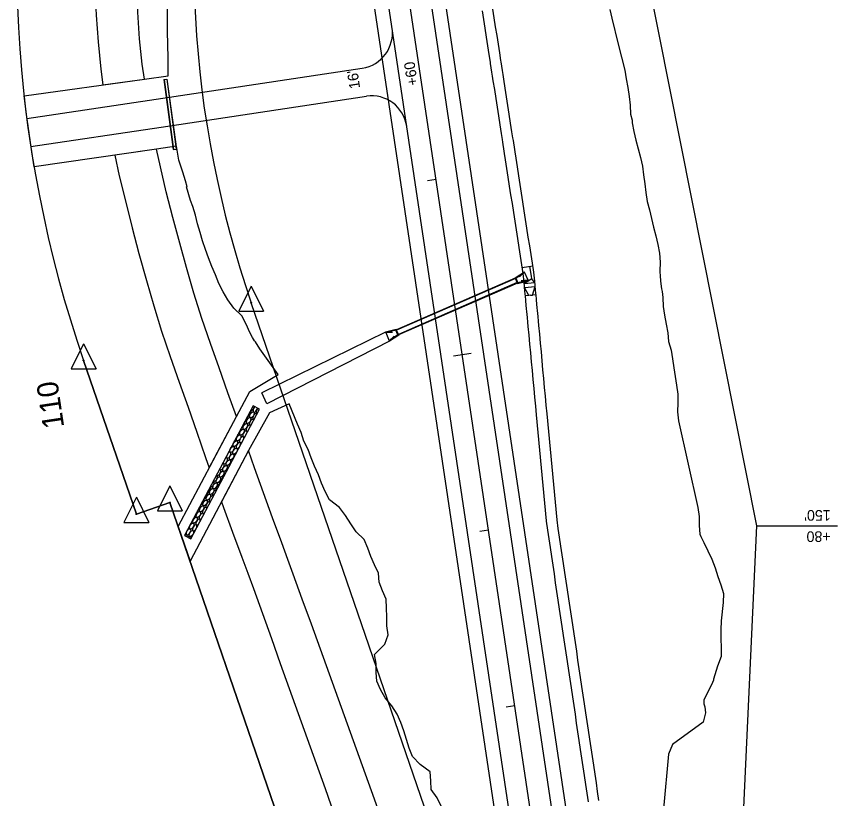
# Model space of a CAD drawing. Extents: x 609264 to 611265, y 427753 to 431566.
# Drawn here: x 610708.3 to 611171.4, y 429032.9 to 429473.9 of the extents above; entities that cross this region are included whole.
import ezdxf

# ---------------------------------------------------------------- set-up
doc = ezdxf.new("R2010")
doc.units = 0
for name, color, linetype in [('R_Drainage', 7, 'Continuous'), ('R_Drainage Stage 2', 7, 'Continuous'), ('R_Drive', 7, 'Continuous'), ('R_Drive Annot', 7, 'Continuous'), ('R_Drive Stage 2', 7, 'Continuous'), ('R_Horz Alg', 7, 'Continuous'), ('R_Horz Alg Station', 7, 'Continuous'), ('R_Horz Alg Station Annot', 7, 'Continuous'), ('R_Obliterate', 7, 'Continuous'), ('R_Proposed Const Limits', 7, 'Continuous'), ('R_Proposed Const Limits S2', 7, 'Continuous'), ('R_Proposed Road', 7, 'Continuous'), ('R_Proposed Shoulder', 7, 'Continuous'), ('R_Restraining Conditions', 7, 'Continuous'), ('R_ROW', 7, 'Continuous'), ('R_ROW Annot', 7, 'Continuous'), ('S_EXIST_ROW', 7, 'Continuous')]:
    doc.layers.add(name, color=color, linetype=linetype)

msp = doc.modelspace()

# ---------------------------------------------------------------- linework, layer by layer
at = {"layer": 'R_Drainage'}
for p, q in [((610791.37, 429438.24), (610793.18, 429438.48)), ((610791.37, 429438.24), (610796.67, 429398.8)), ((610791.53, 429438.26), (610796.84, 429398.83)), ((610793.02, 429438.46), (610798.32, 429399.03)), ((610793.18, 429438.48), (610798.49, 429399.05)), ((610796.67, 429398.8), (610798.49, 429399.05)), ((610993.59, 429332.28), (610999.53, 429333.21)), ((610989.54, 429326.52), (610994.76, 429329.97)), ((610989.93, 429326.33), (610994.88, 429329.7)), ((610994.76, 429329.97), (610992.04, 429327.02)), ((610994.88, 429329.7), (610992.04, 429327.02)), ((610994.88, 429329.7), (610994.76, 429329.97)), ((610996.87, 429325.12), (610994.88, 429329.7)), ((610989.63, 429326.3), (610922.6, 429297.15)), ((610989.72, 429326.09), (610922.7, 429296.94)), ((610990.72, 429323.8), (610923.69, 429294.64)), ((610990.81, 429323.59), (610923.79, 429294.43)), ((610989.65, 429326.25), (610989.54, 429326.52)), ((610989.92, 429326.37), (610989.65, 429326.25)), ((610989.65, 429326.25), (610990.79, 429323.65)), ((610989.92, 429326.37), (610991.05, 429323.77)), ((610991.05, 429323.77), (610990.79, 429323.65)), ((610990.79, 429323.65), (610990.9, 429323.38)), ((610990.9, 429323.38), (610996.99, 429324.85)), ((610991.04, 429323.8), (610996.87, 429325.12)), ((610996.87, 429325.12), (610992.97, 429324.87)), ((610996.99, 429324.85), (610992.97, 429324.87)), ((611000.68, 429323.62), (610994.71, 429323.06)), ((610996.87, 429325.12), (610996.99, 429324.85)), ((610994.9, 429321.06), (611000.87, 429321.62)), ((611001.31, 429316.97), (610995.33, 429316.41)), ((610916.42, 429295.89), (610846.72, 429261.7)), ((610922.51, 429297.36), (610916.42, 429295.89)), ((610916.54, 429295.62), (610916.42, 429295.89)), ((610916.42, 429295.89), (610920.44, 429295.88)), ((610922.37, 429296.95), (610916.54, 429295.62)), ((610916.54, 429295.62), (610920.44, 429295.88)), ((610916.54, 429295.62), (610918.54, 429291.05)), ((610922.36, 429296.98), (610922.63, 429297.09)), ((610923.49, 429294.38), (610922.36, 429296.98)), ((610922.63, 429297.09), (610922.51, 429297.36)), ((610923.76, 429294.49), (610922.63, 429297.09)), ((610923.49, 429294.38), (610923.76, 429294.49)), ((610923.76, 429294.49), (610923.88, 429294.23)), ((610923.48, 429294.41), (610918.54, 429291.05)), ((610918.54, 429291.05), (610921.38, 429293.72)), ((610918.54, 429291.05), (610918.65, 429290.78)), ((610923.88, 429294.23), (610918.65, 429290.78)), ((610918.65, 429290.78), (610921.38, 429293.72))]:
    msp.add_line(p, q, dxfattribs=at)
for points in [[(611007.21, 429189.51), (611001.62, 429249.25), (611001.16, 429254.24), (611000.69, 429259.23), (611000.23, 429264.21), (610999.76, 429269.2), (610999.29, 429274.18), (610998.83, 429279.17), (610998.36, 429284.16), (610997.9, 429289.14), (610997.43, 429294.13), (610996.96, 429299.11), (610996.74, 429301.49), (610996.5, 429304.1), (610996.17, 429307.6), (610996.03, 429309.09), (610995.63, 429313.38), (610995.56, 429314.07), (610995.38, 429316.07), (610995.1, 429319.06), (610994.63, 429324.03), (610994.12, 429328.91), (610993.36, 429333.78), (610992.59, 429338.72), (610991.83, 429343.66), (610991.06, 429348.6), (610990.29, 429353.54), (610989.53, 429358.48), (610988.76, 429363.43), (610987.99, 429368.37), (610987.22, 429373.31), (610986.46, 429378.25), (610985.69, 429383.19), (610984.92, 429388.13), (610984.16, 429393.07), (610983.61, 429396.62), (610983.6, 429396.63), (610983.39, 429398.01), (610982.62, 429402.95), (610982.39, 429404.45), (610982.39, 429404.46), (610981.85, 429407.89), (610981.09, 429412.83), (610980.32, 429417.77), (610979.55, 429422.72), (610978.79, 429427.66), (610978.02, 429432.6), (610977.25, 429437.54), (610976.83, 429440.22), (610976.48, 429442.48), (610975.72, 429447.42), (610975.62, 429448.06), (610974.95, 429452.36), (610974.18, 429457.3), (610973.42, 429462.24), (610972.65, 429467.18), (610971.88, 429472.12), (610971.11, 429477.07)], [(611013.18, 429190.06), (611007.6, 429249.81), (611007.13, 429254.8), (611006.67, 429259.78), (611006.2, 429264.77), (611005.73, 429269.76), (611005.27, 429274.74), (611004.8, 429279.73), (611004.34, 429284.71), (611003.87, 429289.7), (611003.4, 429294.69), (611002.94, 429299.67), (611002.72, 429302.04), (611002.47, 429304.66), (611002.14, 429308.16), (611002, 429309.64), (611001.6, 429313.94), (611001.54, 429314.63), (611001.35, 429316.62), (611001.07, 429319.62), (611000.6, 429324.62), (611000.07, 429329.69), (610999.29, 429334.7), (610998.52, 429339.64), (610997.76, 429344.58), (610996.99, 429349.52), (610996.22, 429354.46), (610995.45, 429359.4), (610994.69, 429364.35), (610993.92, 429369.29), (610993.15, 429374.23), (610992.39, 429379.17), (610991.62, 429384.11), (610990.85, 429389.05), (610990.08, 429393.99), (610989.53, 429397.54), (610989.53, 429397.55), (610989.32, 429398.93), (610988.55, 429403.87), (610988.32, 429405.37), (610988.32, 429405.38), (610987.78, 429408.81), (610987.02, 429413.75), (610986.25, 429418.7), (610985.48, 429423.64), (610984.71, 429428.58), (610983.95, 429433.52), (610983.18, 429438.46), (610982.76, 429441.14), (610982.41, 429443.4), (610981.65, 429448.34), (610981.55, 429448.98), (610980.88, 429453.28), (610980.11, 429458.22), (610979.34, 429463.16), (610978.58, 429468.1), (610977.81, 429473.05), (610977.04, 429477.99)], [(610998.94, 429326.02), (610998.79, 429327.39), (610997.93, 429332.96)], [(611000.68, 429323.62), (610998.94, 429326.02), (610998.94, 429326.02), (610994.71, 429323.06)], [(610998.32, 429316.69), (610997.32, 429316.6), (610994.9, 429321.06)], [(610998.32, 429316.69), (610999.32, 429316.78), (611000.87, 429321.62)], [(610918.65, 429290.78), (610849.48, 429255.54), (610846.72, 429261.7)], [(611030.92, 429031.02), (611030.18, 429035.97), (611029.44, 429040.91), (611028.7, 429045.86), (611027.96, 429050.8), (611027.22, 429055.75), (611026.48, 429060.69), (611025.74, 429065.64), (611025, 429070.58), (611024.26, 429075.53), (611023.52, 429080.47), (611022.78, 429085.41), (611022.04, 429090.36), (611021.3, 429095.3), (611020.56, 429100.25), (611019.82, 429105.19), (611019.08, 429110.14), (611018.34, 429115.08), (611017.6, 429120.03), (611016.86, 429124.97), (611016.12, 429129.92), (611015.38, 429134.86), (611014.64, 429139.81), (611013.9, 429144.75), (611013.16, 429149.7), (611012.42, 429154.64), (611011.68, 429159.59), (611010.94, 429164.53), (611010.2, 429169.48), (611009.46, 429174.42), (611008.72, 429179.37), (611007.98, 429184.31), (611007.23, 429189.34)], [(611036.85, 429031.91), (611036.11, 429036.85), (611035.37, 429041.8), (611034.63, 429046.74), (611033.89, 429051.69), (611033.15, 429056.63), (611032.41, 429061.58), (611031.67, 429066.52), (611030.93, 429071.47), (611030.19, 429076.41), (611029.45, 429081.36), (611028.71, 429086.3), (611027.97, 429091.25), (611027.23, 429096.19), (611026.49, 429101.14), (611025.75, 429106.08), (611025.01, 429111.03), (611024.27, 429115.97), (611023.53, 429120.92), (611022.79, 429125.86), (611022.05, 429130.81), (611021.31, 429135.75), (611020.57, 429140.7), (611019.83, 429145.64), (611019.09, 429150.59), (611018.35, 429155.53), (611017.61, 429160.48), (611016.87, 429165.42), (611016.13, 429170.37), (611015.39, 429175.31), (611014.65, 429180.26), (611013.91, 429185.2), (611013.18, 429190.06)]]:
    msp.add_lwpolyline(points, dxfattribs=at)
at = {"layer": 'R_Drainage Stage 2'}
for p, q in [((610841.76, 429254.38), (610803.09, 429181.2)), ((610845.3, 429252.51), (610841.76, 429254.38)), ((610806.62, 429179.33), (610845.3, 429252.51)), ((610803.09, 429181.2), (610806.62, 429179.33))]:
    msp.add_line(p, q, dxfattribs=at)
for centre, start_param, end_param in [((610841.31, 429253.49), 3.198655, 5.290171), ((610842.99, 429252.52), 0.98539, 5.33654), ((610844.68, 429251.55), 0.937483, 3.319225), ((610837.56, 429247), 3.490368, 6.078633), ((610839.44, 429250.24), 3.343115, 6.225887), ((610842.8, 429248.3), 6.103212, 9.748974), ((610835.68, 429243.75), 3.644118, 5.924884), ((610839.05, 429241.8), 5.787685, 10.064502), ((610840.92, 429245.05), 5.950838, 9.901349), ((610833.81, 429240.5), 3.809715, 5.759287), ((610837.17, 429238.55), 5.605187, 10.246999), ((610830.06, 429234), 4.228822, 5.34018), ((610831.93, 429237.25), 3.996754, 5.572248), ((610835.3, 429235.31), 5.383647, 10.46854), ((610828.18, 429230.75), 4.671667, 4.897335), ((610833.42, 429232.06), 5.030411, 10.821776), ((610826.11, 429223.28), 2.419988, 7.149013), ((610827.99, 429226.53), 2.184163, 7.384838), ((610831.35, 429224.59), 0.900272, 2.385544), ((610833.23, 429227.84), 1.149634, 2.136182), ((610824.24, 429220.03), 2.608579, 6.960423), ((610829.48, 429221.34), 0.706382, 2.579434), ((610822.36, 429216.78), 2.775, 6.794001), ((610825.73, 429214.84), 0.381413, 2.904403), ((610827.6, 429218.09), 0.537189, 2.748628), ((610818.61, 429210.29), 3.076707, 6.492295), ((610820.49, 429213.54), 2.929214, 6.639787), ((610823.85, 429211.59), 0.233101, 3.052716), ((610816.73, 429207.04), 3.221234, 6.347768), ((610820.1, 429205.1), 6.227043, 9.625144), ((610821.97, 429208.34), 0.088308, 3.197508), ((610812.98, 429200.54), 3.51392, 6.055081), ((610814.86, 429203.79), 3.365919, 6.203082), ((610818.22, 429201.85), 6.079825, 9.772362), ((610811.11, 429197.29), 3.669108, 5.899894), ((610816.35, 429198.6), 5.926145, 9.926042), ((610809.23, 429194.04), 3.837258, 5.731744), ((610812.6, 429192.1), 5.573864, 10.278322), ((610814.47, 429195.35), 5.760672, 10.091515), ((610805.48, 429187.55), 4.273224, 5.295777), ((610807.36, 429190.79), 4.029137, 5.539865), ((610810.72, 429188.85), 5.34235, 10.509837), ((610805.29, 429183.33), 1.850243, 7.718758), ((610808.85, 429185.6), 4.907098, 10.945089), ((610803.41, 429180.08), 5.198242, 7.342493), ((610805.09, 429179.11), 5.242117, 7.362998), ((610806.78, 429178.13), 0.867464, 1.034831), ((610808.65, 429181.38), 1.103882, 2.181934)]:
    msp.add_ellipse(centre, major_axis=(0.94, 1.62), ratio=0.517889, start_param=start_param, end_param=end_param, dxfattribs=at)
for centre in [(610841.12, 429249.27), (610837.37, 429242.77), (610839.24, 429246.02), (610835.49, 429239.53), (610831.74, 429233.03), (610833.62, 429236.28), (610829.86, 429229.78), (610831.55, 429228.81), (610829.67, 429225.56), (610825.92, 429219.06), (610827.8, 429222.31), (610824.04, 429215.81), (610820.29, 429209.32), (610822.17, 429212.56), (610818.42, 429206.07), (610816.54, 429202.82), (610812.79, 429196.32), (610814.67, 429199.57), (610810.91, 429193.07), (610807.16, 429186.57), (610809.04, 429189.82), (610806.97, 429182.35)]:
    msp.add_ellipse(centre, major_axis=(0.94, 1.62), ratio=0.517889, dxfattribs=at)
at = {"layer": 'R_Drive'}
for p, q in [((610787.05, 429427.3), (610903.29, 429444.69)), ((610789.88, 429411.54), (610905.66, 429428.87))]:
    msp.add_line(p, q, dxfattribs=at)
for centre, start, end in [((610900.34, 429464.47), 278.51, 8.51), ((610908.62, 429409.09), 8.51, 98.51)]:
    msp.add_arc(centre, 20, start, end, dxfattribs=at)
at = {"layer": 'R_Drive Stage 2'}
for p, q in [((610714.12, 429416.38), (610787.05, 429427.3)), ((610716.37, 429400.54), (610789.88, 429411.54))]:
    msp.add_line(p, q, dxfattribs=at)
msp.add_arc((611404.88, 429506.52), 696.62, 187.43434, 188.75038, dxfattribs=at)
at = {"layer": 'R_Horz Alg'}
msp.add_line((611107.78, 428294.28), (610909.26, 429621.04), dxfattribs=at)
at = {"layer": 'R_Horz Alg Station'}
for points in [[(610940.06, 429381.43), (610945.01, 429382.17)], [(610954.86, 429282.53), (610964.75, 429284.01)], [(610969.66, 429183.64), (610974.6, 429184.38)], [(610984.45, 429084.74), (610989.4, 429085.48)]]:
    msp.add_lwpolyline(points, dxfattribs=at)
at = {"layer": 'R_Obliterate'}
for p, q in [((610757.08, 429435.37), (610780.44, 429438.59)), ((610787.33, 429399.08), (610763.81, 429395.68)), ((610787.33, 429399.08), (610763.81, 429395.68)), ((610817.06, 429219.41), (610832.32, 429248.29)), ((610839.19, 429229.17), (610823.9, 429200.25))]:
    msp.add_line(p, q, dxfattribs=at)
for points in [[(610780.44, 429438.59), (610779.25, 429447.05), (610777.75, 429461.34), (610776.75, 429476.28), (610776.18, 429490.93), (610775.96, 429505.05), (610776.14, 429520.02), (610776.84, 429534.46), (610777.93, 429549.4), (610779, 429561.16)], [(610752.6, 429520.59), (610752.23, 429505.61), (610752.46, 429489.81), (610753.17, 429474.53), (610754.29, 429459.61), (610755.88, 429444.15), (610757.08, 429435.37)], [(610832.32, 429248.29), (610827.58, 429261.61), (610822.56, 429275.73), (610817.72, 429289.49), (610812.86, 429303.63), (610808.38, 429317.92), (610804.17, 429332.29), (610800.36, 429346.04), (610796.49, 429360.48), (610792.82, 429375), (610789.48, 429389.16), (610787.33, 429399.08)], [(610832.32, 429248.29), (610827.58, 429261.61), (610822.56, 429275.73), (610817.72, 429289.49), (610812.86, 429303.63), (610808.38, 429317.92), (610804.17, 429332.29), (610800.36, 429346.04), (610796.49, 429360.48), (610792.82, 429375), (610789.48, 429389.16), (610787.33, 429399.08)], [(610763.81, 429395.68), (610766.28, 429384.07), (610769.96, 429369.13), (610773.64, 429354.61), (610777.4, 429340.14), (610781.56, 429325.06), (610785.74, 429310.69), (610790.18, 429296.41), (610795.02, 429282.24), (610800.06, 429267.75), (610805.05, 429253.64), (610810.1, 429239.42), (610814.97, 429225.28), (610817.06, 429219.41)], [(610763.81, 429395.68), (610766.28, 429384.07), (610769.96, 429369.13), (610773.64, 429354.61), (610777.4, 429340.14), (610781.56, 429325.06), (610785.74, 429310.69), (610790.18, 429296.41), (610795.02, 429282.24), (610800.06, 429267.75), (610805.05, 429253.64), (610810.1, 429239.42), (610814.97, 429225.28), (610817.06, 429219.41)], [(610949.74, 428919.39), (610944.79, 428933.54), (610939.84, 428947.68), (610934.89, 428961.84), (610929.95, 428976), (610925.03, 428990.09), (610920.12, 429004.24), (610915.22, 429018.41), (610910.28, 429032.53), (610905.2, 429046.79), (610900.13, 429060.88), (610895.06, 429074.96), (610889.94, 429089.04), (610884.83, 429103.09), (610879.7, 429117.17), (610874.63, 429131.27), (610869.49, 429145.36), (610864.32, 429159.44), (610861.3, 429167.65), (610857.91, 429177.14), (610852.75, 429191.2), (610847.64, 429205.34), (610842.61, 429219.43), (610839.19, 429229.17)], [(610949.74, 428919.39), (610944.79, 428933.54), (610939.84, 428947.68), (610934.89, 428961.84), (610929.95, 428976), (610925.03, 428990.09), (610920.12, 429004.24), (610915.22, 429018.41), (610910.28, 429032.53), (610905.2, 429046.79), (610900.13, 429060.88), (610895.06, 429074.96), (610889.94, 429089.04), (610884.83, 429103.09), (610879.7, 429117.17), (610874.63, 429131.27), (610869.49, 429145.36), (610864.32, 429159.44), (610861.3, 429167.65), (610857.91, 429177.14), (610852.75, 429191.2), (610847.64, 429205.34), (610842.61, 429219.43), (610839.19, 429229.17)], [(610823.9, 429200.25), (610825.02, 429197.1), (610830.11, 429183.12), (610835.44, 429169.12), (610838.88, 429160.1), (610842.06, 429151.34), (610847.14, 429137.26), (610852.18, 429123.19), (610857.11, 429109.05), (610862.14, 429094.95), (610867.22, 429080.86), (610872.19, 429066.72), (610877.27, 429052.63), (610882.37, 429038.56), (610887.37, 429024.62)], [(610823.9, 429200.25), (610825.02, 429197.1), (610830.11, 429183.12), (610835.44, 429169.12), (610838.88, 429160.1), (610842.06, 429151.34), (610847.14, 429137.26), (610852.18, 429123.19), (610857.11, 429109.05), (610862.14, 429094.95), (610867.22, 429080.86), (610872.19, 429066.72), (610877.27, 429052.63), (610882.37, 429038.56), (610887.37, 429024.62)]]:
    msp.add_lwpolyline(points, dxfattribs=at)
at = {"layer": 'R_Proposed Const Limits'}
msp.add_line((610799.53, 429186.24), (610806.22, 429166.79), dxfattribs=at)
for points in [[(610780.44, 429438.59), (610793.86, 429440.45), (610793.8, 429445.49), (610793.84, 429450.56), (610793.46, 429465.43), (610793.45, 429465.67), (610793.43, 429470.72), (610793.61, 429485.91), (610793.78, 429490.99), (610793.9, 429501.12), (610794.52, 429506.27), (610794.82, 429511.37), (610795.03, 429516.46), (610795.33, 429521.56), (610795.79, 429526.68), (610796.02, 429531.77), (610796.36, 429536.88), (610797.31, 429542.08), (610798.22, 429552.33), (610798.86, 429557.48), (610799.3, 429562.6), (610799.71, 429567.72), (610800.73, 429572.92), (610804.25, 429598.73)], [(611042.98, 429477.72), (611044.18, 429472.85), (611047.77, 429458.22), (611051.37, 429443.59), (611052.26, 429438.67), (611053.13, 429433.74), (611053.9, 429428.8), (611054.48, 429423.83), (611054.72, 429418.81), (611055.51, 429415.42), (611055.56, 429413.88), (611056.53, 429408.97), (611057.71, 429404.09), (611059.01, 429399.23), (611060.32, 429394.37), (611061.49, 429389.49), (611062.05, 429384.52), (611062.63, 429379.55), (611063.2, 429374.58), (611063.99, 429369.64), (611065.31, 429364.79), (611066.44, 429359.9), (611067.65, 429355.02), (611068.86, 429350.15), (611070.06, 429345.27), (611070.93, 429340.35), (611071.31, 429335.35), (611071.24, 429330.28), (611071.4, 429327.27), (611071.55, 429325.27), (611071.62, 429324.58), (611072.2, 429320.31), (611072.42, 429318.84), (611072.87, 429315.36), (611073.12, 429310.34), (611073.86, 429305.4), (611074.75, 429300.47), (611075.64, 429295.55), (611076.12, 429290.57), (611077.5, 429285.72), (611078.33, 429280.79), (611079.06, 429275.84), (611079.84, 429270.9), (611080.62, 429265.96), (611081.4, 429261.02), (611081.4, 429255.97), (611081.23, 429250.89), (611081.73, 429245.91), (611092.7, 429196.99), (611093.31, 429192.03), (611093.38, 429186.98), (611093.71, 429181.97), (611094.25, 429180.76), (611095.98, 429177.26), (611098.33, 429172.55), (611100.55, 429167.83), (611102.3, 429163.04), (611103.95, 429158.23), (611105.59, 429153.42), (611107.15, 429148.6), (611106.96, 429143.51), (611105.75, 429133.22), (611105.52, 429128.13), (611105.68, 429112.99), (611103.77, 429107.65), (611101.37, 429100.21), (611101.47, 429099.77), (611100.38, 429097.03), (611097.56, 429091.55), (611096.06, 429088.49), (611096.07, 429086.27), (611096.54, 429084.73), (611097.02, 429081.36), (611095.68, 429076.1), (611078.25, 429063.38), (611075.99, 429057.99), (611073.3, 429027.25)], [(610799.53, 429186.24), (610832.32, 429248.29), (610839.91, 429262.42), (610855.94, 429272.06), (610845.62, 429286.41), (610843.06, 429290.38), (610842.58, 429291.01), (610841.38, 429292.86), (610839.98, 429295.68), (610837.84, 429300.41), (610835.37, 429305.1), (610830.95, 429309.49), (610827.48, 429314.03), (610824.94, 429318.71), (610822.42, 429323.39), (610820.57, 429328.16), (610818.48, 429332.91), (610816.69, 429337.7), (610814.89, 429342.48), (610813.3, 429347.3), (610811.85, 429352.14), (610810.44, 429356.98), (610809.19, 429361.85), (610807.71, 429366.69), (610806.51, 429370.14), (610804.2, 429377.81), (610804.49, 429377.86), (610803.54, 429381.23), (610802.14, 429386.08), (610799.85, 429392.79), (610798.64, 429400.72), (610787.33, 429399.08)], [(610947.79, 429028.69), (610945.54, 429033.41), (610942.22, 429037.97), (610941.95, 429042.99), (610941.64, 429048), (610935.93, 429052.2), (610931.71, 429056.62), (610929.88, 429061.4), (610928.31, 429066.23), (610926.75, 429071.05), (610925.17, 429075.87), (610922.93, 429080.59), (610920.03, 429085.21), (610916.22, 429089.69), (610913.62, 429094.36), (610911.56, 429099.11), (610911.12, 429104.1), (610911.17, 429109.16), (610910.28, 429114.08), (610916.11, 429120.01), (610917.96, 429125.34), (610917.19, 429130.28), (610917.13, 429135.33), (610916.99, 429140.37), (610916.79, 429145.39), (610914.71, 429150.14), (610912.96, 429154.93), (610912.58, 429159.93), (610910.32, 429164.65), (610908.08, 429169.37), (610906.55, 429174.19), (610904.35, 429178.92), (610899.86, 429183.3), (610896.91, 429187.92), (610893.89, 429192.52), (610890.56, 429197.08), (610884.93, 429201.29), (610882.39, 429205.97), (610880.41, 429210.73), (610878.62, 429215.52), (610876.47, 429220.25), (610874.51, 429225.01), (610872.8, 429229.81), (610870.46, 429234.52), (610868.94, 429239.35), (610866.85, 429244.09), (610862.02, 429255.49), (610851.09, 429250.37), (610839.19, 429229.17), (610806.22, 429166.79)]]:
    msp.add_lwpolyline(points, dxfattribs=at)
at = {"layer": 'R_Proposed Const Limits S2'}
msp.add_lwpolyline([(610787.33, 429399.08), (610718.23, 429389.1), (610714.8, 429411.32), (610712.57, 429429.21), (610780.44, 429438.59)], dxfattribs=at)
at = {"layer": 'R_Proposed Road'}
for p, q in [((611041.57, 428655.73), (610897.4, 429619.26)), ((611100.64, 428423.11), (610921.13, 429622.82))]:
    msp.add_line(p, q, dxfattribs=at)
at = {"layer": 'R_Proposed Shoulder'}
for p, q in [((611112.77, 428396.14), (610929.04, 429624)), ((611025.84, 428706.82), (610889.48, 429618.08))]:
    msp.add_line(p, q, dxfattribs=at)
at = {"layer": 'R_Restraining Conditions'}
for p, q in [((610746.15, 429279.9), (610775.93, 429193.35)), ((610794.84, 429199.86), (610963.05, 428710.9))]:
    msp.add_line(p, q, dxfattribs=at)
msp.add_lwpolyline([(610775.93, 429193.35), (610794.84, 429199.86)], dxfattribs=at)
msp.add_arc((611404.88, 429506.52), 696.62, 167.41778, 198.98444, dxfattribs=at)
at = {"layer": 'R_ROW'}
msp.add_lwpolyline([(611107.97, 428799.88), (611125.91, 429186.79), (611015.56, 429741.88)], dxfattribs=at)
at = {"layer": 'R_ROW Annot'}
msp.add_line((611125.91, 429186.79), (611171.43, 429186.79), dxfattribs=at)
at = {"layer": 'S_EXIST_ROW'}
for p, q in [((610840.74, 429321.89), (610833.69, 429307.7)), ((610840.74, 429321.89), (610847.72, 429307.7)), ((611038.7, 428736.93), (610840.72, 429312.43)), ((610840.72, 429312.43), (610840.72, 429312.43)), ((610833.69, 429307.7), (610847.72, 429307.7)), ((610746.18, 429289.36), (610739.13, 429275.17)), ((610746.18, 429289.36), (610753.16, 429275.17)), ((610775.93, 429193.35), (610746.15, 429279.9)), ((610746.15, 429279.9), (610746.15, 429279.9)), ((610739.13, 429275.17), (610753.16, 429275.17)), ((610794.87, 429209.31), (610787.82, 429195.13)), ((610794.87, 429209.31), (610801.84, 429195.13)), ((610775.96, 429202.8), (610768.9, 429188.62)), ((610775.96, 429202.8), (610782.93, 429188.62)), ((610963.05, 428710.9), (610794.84, 429199.86)), ((610794.84, 429199.86), (610794.84, 429199.86)), ((610775.93, 429193.35), (610775.93, 429193.35)), ((610787.82, 429195.13), (610801.84, 429195.13)), ((610768.9, 429188.62), (610782.93, 429188.62))]:
    msp.add_line(p, q, dxfattribs=at)
msp.add_lwpolyline([(610794.84, 429199.86), (610775.93, 429193.35)], dxfattribs=at)
for centre, radius in [((610840.72, 429312.43), 0.24), ((610840.72, 429312.43), 0.12), ((610746.15, 429279.9), 0.24), ((610746.15, 429279.9), 0.12), ((610794.84, 429199.86), 0.24), ((610794.84, 429199.86), 0.12), ((610775.93, 429193.35), 0.24), ((610775.93, 429193.35), 0.12)]:
    msp.add_circle(centre, radius, dxfattribs=at)
for radius in [696.62, 596.62]:
    msp.add_arc((611404.88, 429506.52), radius, 167.41778, 198.98444, dxfattribs=at)

# ---------------------------------------------------------------- texts
at = {"layer": 'R_Drive Annot'}
for s, rotation, p in [('+60', 99.0593, (610934.83, 429435.33)), ("16'", 98.6267, (610902.16, 429433.52))]:
    msp.add_text(s, height=6, rotation=rotation, dxfattribs=at).set_placement(p)
at = {"layer": 'R_Horz Alg Station Annot'}
msp.add_text('110', height=12, rotation=98.51, dxfattribs=at).set_placement((610735.27, 429242.42))
at = {"layer": 'R_ROW Annot'}
for s, p in [("150'", (611167.54, 429195.61)), ('+80', (611167.54, 429183.61))]:
    msp.add_text(s, height=6, rotation=180, dxfattribs=at).set_placement(p)

doc.saveas('drawing.dxf')
